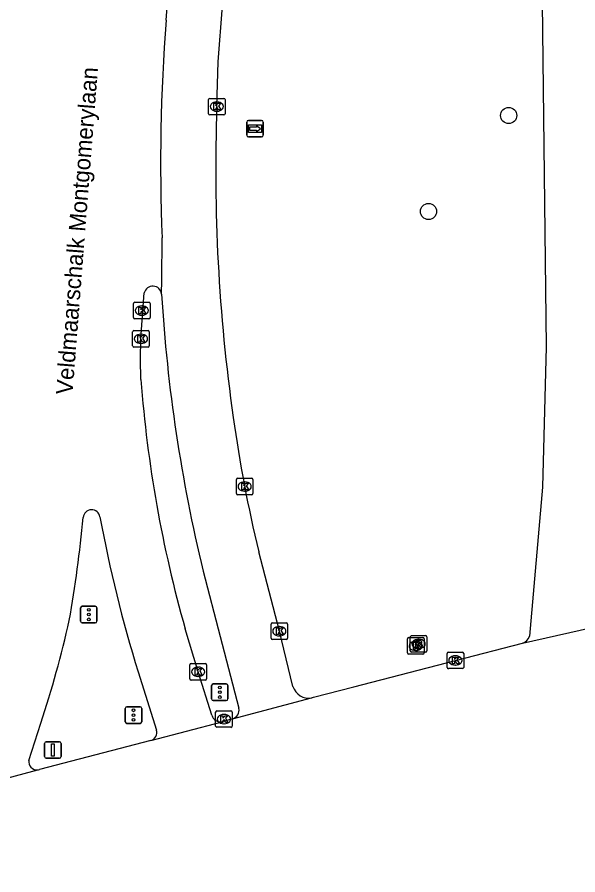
# Model space of a CAD drawing. Extents: x 160806 to 161707, y 383697 to 384148.
# Drawn here: x 161203.1 to 161236.9, y 383921.9 to 383973.8 of the extents above; entities that cross this region are included whole.
import ezdxf

# ---------------------------------------------------------------- set-up
doc = ezdxf.new("R2010")
doc.units = 0
for name, color, linetype in [('IMGEO_Boom', 7, 'Continuous'), ('IMGEO_Kolk', 7, 'Continuous'), ('IMGEO_Openbare_ruimte_label', 7, 'Continuous'), ('IMGEO_OVBaan_gesloten', 7, 'Continuous'), ('IMGEO_Portaal', 7, 'Continuous'), ('IMGEO_Rijbaan_lokaal_gesloten', 7, 'Continuous'), ('IMGEO_Rioolput', 7, 'Continuous'), ('IMGEO_Verkeersregelinstallatiepaal', 7, 'Continuous'), ('IMGEO_Wegwijzer', 7, 'Continuous')]:
    doc.layers.add(name, color=color, linetype=linetype)

msp = doc.modelspace()

# ---------------------------------------------------------------- linework, layer by layer
at = {"layer": 'IMGEO_Boom'}
for centre in [(161232.756, 383967.827), (161227.918, 383962.027)]:
    msp.add_circle(centre, 0.489, dxfattribs=at)
at = {"layer": 'IMGEO_Kolk'}
for p, q in [((161214.636, 383967.938), (161214.636, 383968.79)), ((161214.711, 383968.864), (161215.563, 383968.864)), ((161215.124, 383968.644), (161215.149, 383968.644)), ((161215.637, 383968.79), (161215.637, 383967.938)), ((161215.147, 383968.084), (161215.122, 383968.084)), ((161215.563, 383967.864), (161214.711, 383967.864)), ((161210.106, 383955.61), (161210.106, 383956.462)), ((161210.181, 383956.536), (161211.033, 383956.536)), ((161210.594, 383956.316), (161210.619, 383956.316)), ((161211.107, 383956.462), (161211.107, 383955.61)), ((161210.617, 383955.756), (161210.592, 383955.756)), ((161211.033, 383955.536), (161210.181, 383955.536)), ((161210.051, 383953.904), (161210.051, 383954.756)), ((161210.126, 383954.83), (161210.978, 383954.83)), ((161210.539, 383954.61), (161210.564, 383954.61)), ((161211.052, 383954.756), (161211.052, 383953.904)), ((161210.978, 383953.83), (161210.126, 383953.83)), ((161210.562, 383954.05), (161210.537, 383954.05)), ((161216.313, 383944.977), (161216.313, 383945.829)), ((161216.388, 383945.903), (161217.24, 383945.903)), ((161217.314, 383945.829), (161217.314, 383944.977)), ((161216.801, 383945.683), (161216.826, 383945.683)), ((161217.24, 383944.903), (161216.388, 383944.903)), ((161216.824, 383945.123), (161216.799, 383945.123)), ((161218.408, 383936.232), (161218.408, 383937.084)), ((161218.483, 383937.158), (161219.335, 383937.158)), ((161219.409, 383937.084), (161219.409, 383936.232)), ((161218.896, 383936.938), (161218.921, 383936.938)), ((161219.335, 383936.158), (161218.483, 383936.158)), ((161218.919, 383936.378), (161218.894, 383936.378)), ((161229.041, 383934.469), (161229.041, 383935.321)), ((161229.116, 383935.395), (161229.968, 383935.395)), ((161229.529, 383935.175), (161229.554, 383935.175)), ((161230.042, 383935.321), (161230.042, 383934.469)), ((161213.508, 383933.781), (161213.508, 383934.633)), ((161213.583, 383934.707), (161214.435, 383934.707)), ((161213.996, 383934.487), (161214.021, 383934.487)), ((161214.509, 383934.633), (161214.509, 383933.781)), ((161229.968, 383934.395), (161229.116, 383934.395)), ((161229.552, 383934.615), (161229.527, 383934.615)), ((161214.019, 383933.927), (161213.994, 383933.927)), ((161214.435, 383933.707), (161213.583, 383933.707)), ((161215.137, 383931.849), (161215.989, 383931.849)), ((161215.062, 383930.923), (161215.062, 383931.775)), ((161215.55, 383931.629), (161215.575, 383931.629)), ((161216.063, 383931.775), (161216.063, 383930.923)), ((161215.989, 383930.849), (161215.137, 383930.849)), ((161215.573, 383931.069), (161215.548, 383931.069))]:
    msp.add_line(p, q, dxfattribs=at)
for points in [[(161214.636, 383967.938), (161214.636, 383968.79)], [(161214.711, 383968.864), (161215.563, 383968.864)], [(161215.637, 383968.79), (161215.637, 383967.938)], [(161214.957, 383968.564), (161215.08, 383968.564), (161215.08, 383968.413), (161215.21, 383968.564), (161215.374, 383968.564), (161215.228, 383968.413), (161215.381, 383968.164), (161215.229, 383968.164), (161215.144, 383968.328), (161215.08, 383968.261), (161215.08, 383968.164), (161214.957, 383968.164), (161214.957, 383968.564)], [(161215.563, 383967.864), (161214.711, 383967.864)], [(161210.106, 383955.61), (161210.106, 383956.462)], [(161210.181, 383956.536), (161211.033, 383956.536)], [(161210.427, 383956.236), (161210.55, 383956.236), (161210.55, 383956.085), (161210.68, 383956.236), (161210.844, 383956.236), (161210.698, 383956.085), (161210.851, 383955.836), (161210.699, 383955.836), (161210.614, 383956), (161210.55, 383955.933), (161210.55, 383955.836), (161210.427, 383955.836), (161210.427, 383956.236)], [(161211.107, 383956.462), (161211.107, 383955.61)], [(161211.033, 383955.536), (161210.181, 383955.536)], [(161210.051, 383953.904), (161210.051, 383954.756)], [(161210.126, 383954.83), (161210.978, 383954.83)], [(161211.052, 383954.756), (161211.052, 383953.904)], [(161210.372, 383954.53), (161210.495, 383954.53), (161210.495, 383954.379), (161210.625, 383954.53), (161210.789, 383954.53), (161210.643, 383954.379), (161210.796, 383954.13), (161210.644, 383954.13), (161210.559, 383954.294), (161210.495, 383954.227), (161210.495, 383954.13), (161210.372, 383954.13), (161210.372, 383954.53)], [(161210.978, 383953.83), (161210.126, 383953.83)], [(161216.313, 383944.977), (161216.313, 383945.829)], [(161216.388, 383945.903), (161217.24, 383945.903)], [(161217.314, 383945.829), (161217.314, 383944.977)], [(161216.634, 383945.603), (161216.757, 383945.603), (161216.757, 383945.452), (161216.887, 383945.603), (161217.051, 383945.603), (161216.905, 383945.452), (161217.058, 383945.203), (161216.906, 383945.203), (161216.821, 383945.367), (161216.757, 383945.3), (161216.757, 383945.203), (161216.634, 383945.203), (161216.634, 383945.603)], [(161217.24, 383944.903), (161216.388, 383944.903)], [(161218.408, 383936.232), (161218.408, 383937.084)], [(161218.483, 383937.158), (161219.335, 383937.158)], [(161219.409, 383937.084), (161219.409, 383936.232)], [(161218.729, 383936.858), (161218.852, 383936.858), (161218.852, 383936.707), (161218.982, 383936.858), (161219.146, 383936.858), (161219, 383936.707), (161219.153, 383936.458), (161219.001, 383936.458), (161218.916, 383936.622), (161218.852, 383936.555), (161218.852, 383936.458), (161218.729, 383936.458), (161218.729, 383936.858)], [(161219.335, 383936.158), (161218.483, 383936.158)], [(161229.041, 383934.469), (161229.041, 383935.321)], [(161229.116, 383935.395), (161229.968, 383935.395)], [(161229.362, 383935.095), (161229.485, 383935.095), (161229.485, 383934.944), (161229.615, 383935.095), (161229.779, 383935.095), (161229.633, 383934.944), (161229.786, 383934.695), (161229.634, 383934.695), (161229.549, 383934.859), (161229.485, 383934.792), (161229.485, 383934.695), (161229.362, 383934.695), (161229.362, 383935.095)], [(161230.042, 383935.321), (161230.042, 383934.469)], [(161213.508, 383933.781), (161213.508, 383934.633)], [(161213.583, 383934.707), (161214.435, 383934.707)], [(161213.829, 383934.407), (161213.952, 383934.407), (161213.952, 383934.256), (161214.082, 383934.407), (161214.246, 383934.407), (161214.1, 383934.256), (161214.253, 383934.007), (161214.101, 383934.007), (161214.016, 383934.171), (161213.952, 383934.104), (161213.952, 383934.007), (161213.829, 383934.007), (161213.829, 383934.407)], [(161214.509, 383934.633), (161214.509, 383933.781)], [(161229.968, 383934.395), (161229.116, 383934.395)], [(161214.435, 383933.707), (161213.583, 383933.707)], [(161215.137, 383931.849), (161215.989, 383931.849)], [(161215.062, 383930.923), (161215.062, 383931.775)], [(161215.383, 383931.549), (161215.506, 383931.549), (161215.506, 383931.398), (161215.636, 383931.549), (161215.8, 383931.549), (161215.654, 383931.398), (161215.807, 383931.149), (161215.655, 383931.149), (161215.57, 383931.313), (161215.506, 383931.246), (161215.506, 383931.149), (161215.383, 383931.149), (161215.383, 383931.549)], [(161216.063, 383931.775), (161216.063, 383930.923)], [(161215.989, 383930.849), (161215.137, 383930.849)]]:
    msp.add_lwpolyline(points, dxfattribs=at)
for centre, start, end in [((161214.713, 383968.788), 91.552, 178.448), ((161214.713, 383968.788), 91.552, 178.448), ((161215.561, 383968.788), 1.552, 88.448), ((161215.561, 383968.788), 1.552, 88.448), ((161214.713, 383967.94), 181.552, 268.448), ((161214.713, 383967.94), 181.552, 268.448), ((161215.561, 383967.94), 271.552, 358.448), ((161215.561, 383967.94), 271.552, 358.448), ((161210.183, 383956.46), 91.552, 178.448), ((161210.183, 383956.46), 91.552, 178.448), ((161211.031, 383956.46), 1.552, 88.448), ((161211.031, 383956.46), 1.552, 88.448), ((161210.183, 383955.612), 181.552, 268.448), ((161210.183, 383955.612), 181.552, 268.448), ((161211.031, 383955.612), 271.552, 358.448), ((161211.031, 383955.612), 271.552, 358.448), ((161210.128, 383954.754), 91.552, 178.448), ((161210.128, 383954.754), 91.552, 178.448), ((161210.976, 383954.754), 1.552, 88.448), ((161210.976, 383954.754), 1.552, 88.448), ((161210.128, 383953.906), 181.552, 268.448), ((161210.128, 383953.906), 181.552, 268.448), ((161210.976, 383953.906), 271.552, 358.448), ((161210.976, 383953.906), 271.552, 358.448), ((161216.39, 383945.827), 91.552, 178.448), ((161216.39, 383945.827), 91.552, 178.448), ((161217.238, 383945.827), 1.552, 88.448), ((161217.238, 383945.827), 1.552, 88.448), ((161216.39, 383944.979), 181.552, 268.448), ((161216.39, 383944.979), 181.552, 268.448), ((161217.238, 383944.979), 271.552, 358.448), ((161217.238, 383944.979), 271.552, 358.448), ((161218.485, 383937.082), 91.552, 178.448), ((161218.485, 383937.082), 91.552, 178.448), ((161219.333, 383937.082), 1.552, 88.448), ((161219.333, 383937.082), 1.552, 88.448), ((161218.485, 383936.234), 181.552, 268.448), ((161218.485, 383936.234), 181.552, 268.448), ((161219.333, 383936.234), 271.552, 358.448), ((161219.333, 383936.234), 271.552, 358.448), ((161229.118, 383935.319), 91.552, 178.448), ((161229.118, 383935.319), 91.552, 178.448), ((161229.966, 383935.319), 1.552, 88.448), ((161229.966, 383935.319), 1.552, 88.448), ((161213.585, 383934.631), 91.552, 178.448), ((161213.585, 383934.631), 91.552, 178.448), ((161214.433, 383934.631), 1.552, 88.448), ((161214.433, 383934.631), 1.552, 88.448), ((161229.118, 383934.471), 181.552, 268.448), ((161229.118, 383934.471), 181.552, 268.448), ((161229.966, 383934.471), 271.552, 358.448), ((161229.966, 383934.471), 271.552, 358.448), ((161213.585, 383933.783), 181.552, 268.448), ((161213.585, 383933.783), 181.552, 268.448), ((161214.433, 383933.783), 271.552, 358.448), ((161214.433, 383933.783), 271.552, 358.448), ((161215.139, 383931.773), 91.552, 178.448), ((161215.139, 383931.773), 91.552, 178.448), ((161215.987, 383931.773), 1.552, 88.448), ((161215.987, 383931.773), 1.552, 88.448), ((161215.139, 383930.925), 181.552, 268.448), ((161215.139, 383930.925), 181.552, 268.448), ((161215.987, 383930.925), 271.552, 358.448), ((161215.987, 383930.925), 271.552, 358.448)]:
    msp.add_arc(centre, 0.0765, start, end, dxfattribs=at)
for centre, major_axis, ratio, start_param, end_param in [((161215.123, 383968.364), (-0.387, 0.002), 0.722429, 4.712389, 7.853982), ((161215.148, 383968.364), (-0.39, 0.002), 0.717154, 1.570796, 4.712389), ((161210.593, 383956.036), (-0.387, 0.002), 0.722429, 4.712389, 7.853982), ((161210.618, 383956.036), (-0.39, 0.002), 0.717154, 1.570796, 4.712389), ((161210.538, 383954.33), (-0.387, 0.002), 0.722429, 4.712389, 7.853982), ((161210.563, 383954.33), (-0.39, 0.002), 0.717154, 1.570796, 4.712389), ((161216.8, 383945.403), (-0.387, 0.002), 0.722429, 4.712389, 7.853982), ((161216.825, 383945.403), (-0.39, 0.002), 0.717154, 1.570796, 4.712389), ((161218.895, 383936.658), (-0.387, 0.002), 0.722429, 4.712389, 7.853982), ((161218.92, 383936.658), (-0.39, 0.002), 0.717154, 1.570796, 4.712389), ((161229.528, 383934.895), (-0.387, 0.002), 0.722429, 4.712389, 7.853982), ((161229.553, 383934.895), (-0.39, 0.002), 0.717154, 1.570796, 4.712389), ((161213.995, 383934.207), (-0.387, 0.002), 0.722429, 4.712389, 7.853982), ((161214.02, 383934.207), (-0.39, 0.002), 0.717154, 1.570796, 4.712389), ((161215.549, 383931.349), (-0.387, 0.002), 0.722429, 4.712389, 7.853982), ((161215.574, 383931.349), (-0.39, 0.002), 0.717154, 1.570796, 4.712389)]:
    msp.add_ellipse(centre, major_axis=major_axis, ratio=ratio, start_param=start_param, end_param=end_param, dxfattribs=at)
at = {"layer": 'IMGEO_OVBaan_gesloten'}
for points in [[(161212.071, 383973.586), (161214.441, 384004.323)], [(161215.137, 383968.364), (161215.222, 383971.062), (161216.53, 383988.019), (161217.59, 384002.154)], [(161211.793, 383957.036), (161211.811, 383957.889), (161211.83, 383960.427)], [(161219.729, 383933.32), (161218.909, 383936.658), (161217.663, 383941.452)], [(161214.31, 383940.287), (161215.337, 383936.331), (161216.466, 383931.999)], [(161216.084, 383931.37), (161220.861, 383932.636)]]:
    msp.add_lwpolyline(points, dxfattribs=at)
for centre, radius, start, end in [((161322.247, 383964.986), 110.511, 175.53696, 182.36459), ((161320.498, 383964.509), 105.432, 177.9047, 188.14488), ((161307.986, 383962.928), 96.373, 183.50511, 193.58753), ((161299.612, 383961.128), 84.278, 187.88118, 193.50125), ((161220.669, 383933.597), 0.98, 196.3992, 281.3167), ((161215.942, 383931.887), 0.536, 285.3781, 12.0801)]:
    msp.add_arc(centre, radius, start, end, dxfattribs=at)
at = {"layer": 'IMGEO_Portaal'}
for p, q in [((161204.737, 383929.08), (161204.737, 383929.88)), ((161204.737, 383929.88), (161204.737, 383929.08)), ((161204.837, 383929.98), (161205.627, 383929.98)), ((161205.627, 383929.98), (161204.837, 383929.98)), ((161205.727, 383929.88), (161205.727, 383929.08)), ((161205.727, 383929.08), (161205.727, 383929.88)), ((161205.627, 383928.98), (161204.837, 383928.98)), ((161204.837, 383928.98), (161205.627, 383928.98))]:
    msp.add_line(p, q, dxfattribs=at)
msp.add_lwpolyline([(161205.157, 383929.855), (161205.307, 383929.855), (161205.307, 383929.105), (161205.157, 383929.105), (161205.157, 383929.855)], dxfattribs=at)
for centre, start, end in [((161204.837, 383929.88), 90, 180), ((161204.837, 383929.88), 90, 180), ((161205.627, 383929.88), 0, 90), ((161205.627, 383929.88), 360, 90), ((161204.837, 383929.08), 180, 270), ((161204.837, 383929.08), 180, 270), ((161205.627, 383929.08), 270, 0), ((161205.627, 383929.08), 270, 0)]:
    msp.add_arc(centre, 0.1, start, end, dxfattribs=at)
at = {"layer": 'IMGEO_Rijbaan_lokaal_gesloten'}
for points in [[(161234.263, 384024.171), (161234.492, 383998.945), (161235.013, 383953.847), (161234.793, 383945.355), (161234.023, 383936.363)], [(161210.551, 383951.863), (161210.527, 383953.098), (161210.552, 383954.33), (161210.749, 383957.101)], [(161233.595, 383935.943), (161251.997, 383940.077)], [(161214.826, 383931.579), (161214.009, 383934.207), (161213.226, 383936.804)], [(161220.861, 383932.636), (161220.976, 383932.667), (161223.402, 383933.299), (161229.542, 383934.895), (161233.595, 383935.943)], [(161210.386, 383934.199), (161211.485, 383930.681)], [(161216.084, 383931.37), (161215.456, 383931.183)], [(161203.779, 383928.854), (161204.51, 383931.103)], [(161211.147, 383930.051), (161215.456, 383931.183)], [(161211.147, 383930.051), (161204.418, 383928.292)], [(161178.402, 383921.933), (161183.781, 383922.753), (161204.32, 383928.275)]]:
    msp.add_lwpolyline(points, dxfattribs=at)
for centre, radius, start, end in [((161211.266, 383956.986), 0.53, 5.4349, 167.4397), ((161286.07, 383957.511), 75.73, 184.27689, 195.86841), ((161207.572, 383943.487), 0.512, 9.1292, 174.7041), ((161132.556, 383950.401), 74.822, 349.92486, 354.73388), ((161286.065, 383957.811), 79.277, 190.34993, 197.32795), ((161140.112, 383952.221), 67.772, 341.84401, 347.29156), ((161233.438, 383936.531), 0.609, 284.9675, 343.9515), ((161215.357, 383931.724), 0.55, 195.3077, 280.3877), ((161211.017, 383930.527), 0.493, 285.3402, 18.232), ((161204.282, 383928.781), 0.508, 171.7914, 274.3222), ((161204.283, 383928.777), 0.503, 274.1696, 285.5126)]:
    msp.add_arc(centre, radius, start, end, dxfattribs=at)
at = {"layer": 'IMGEO_Rioolput'}
for p, q in [((161226.646, 383935.347), (161226.646, 383936.199)), ((161226.721, 383936.273), (161227.573, 383936.273)), ((161226.817, 383935.464), (161226.817, 383936.316)), ((161226.892, 383936.39), (161227.744, 383936.39)), ((161227.134, 383936.053), (161227.159, 383936.053)), ((161227.305, 383936.17), (161227.33, 383936.17)), ((161227.647, 383936.199), (161227.647, 383935.347)), ((161227.818, 383936.316), (161227.818, 383935.464)), ((161227.157, 383935.493), (161227.132, 383935.493)), ((161227.328, 383935.61), (161227.303, 383935.61)), ((161227.573, 383935.273), (161226.721, 383935.273)), ((161227.744, 383935.39), (161226.892, 383935.39))]:
    msp.add_line(p, q, dxfattribs=at)
for points in [[(161226.646, 383935.347), (161226.646, 383936.199)], [(161226.721, 383936.273), (161227.573, 383936.273)], [(161226.817, 383935.464), (161226.817, 383936.316)], [(161226.892, 383936.39), (161227.744, 383936.39)], [(161227.235, 383935.971), (161226.983, 383935.973), (161226.983, 383935.573)], [(161227.406, 383936.088), (161227.154, 383936.09), (161227.154, 383935.69)], [(161227.332, 383936.009), (161227.278, 383936.009), (161227.278, 383935.928)], [(161227.647, 383936.199), (161227.647, 383935.347)], [(161227.818, 383936.316), (161227.818, 383935.464)], [(161226.983, 383935.573), (161227.107, 383935.573), (161227.107, 383935.735), (161227.118, 383935.735)], [(161227.161, 383935.892), (161227.107, 383935.892), (161227.107, 383935.811)], [(161227.107, 383935.811), (161227.159, 383935.811)], [(161227.154, 383935.69), (161227.278, 383935.69), (161227.278, 383935.852), (161227.289, 383935.852)], [(161227.165, 383935.706), (161227.236, 383935.573), (161227.376, 383935.573), (161227.311, 383935.699)], [(161227.278, 383935.928), (161227.33, 383935.928)], [(161227.336, 383935.823), (161227.407, 383935.69), (161227.547, 383935.69), (161227.482, 383935.816)], [(161227.573, 383935.273), (161226.721, 383935.273)], [(161227.744, 383935.39), (161226.892, 383935.39)]]:
    msp.add_lwpolyline(points, dxfattribs=at)
for centre, radius, start, end in [((161226.723, 383936.197), 0.0765, 91.552, 178.448), ((161226.723, 383936.197), 0.0765, 91.552, 178.448), ((161226.894, 383936.314), 0.0765, 91.552, 178.448), ((161226.894, 383936.314), 0.0765, 91.552, 178.448), ((161227.234, 383935.861), 0.109, 350.3612, 89.416), ((161227.338, 383935.913), 0.0964, 77.0061, 93.1865), ((161227.352, 383935.97), 0.0378, 276.6634, 79.6772), ((161227.405, 383935.978), 0.109, 350.3612, 89.416), ((161227.403, 383935.978), 0.112, 277.5842, 350.9817), ((161227.571, 383936.197), 0.0765, 1.552, 88.448), ((161227.571, 383936.197), 0.0765, 1.552, 88.448), ((161227.742, 383936.314), 0.0765, 1.552, 88.448), ((161227.742, 383936.314), 0.0765, 1.552, 88.448), ((161226.894, 383935.466), 0.0765, 181.552, 268.448), ((161226.894, 383935.466), 0.0765, 181.552, 268.448), ((161227.117, 383935.682), 0.0533, 26.0293, 88.6989), ((161227.143, 383936), 0.19, 274.7715, 282.9687), ((161227.167, 383935.796), 0.0964, 77.0061, 93.1865), ((161227.181, 383935.853), 0.0378, 276.6634, 79.6772), ((161227.232, 383935.861), 0.112, 277.5842, 350.9817), ((161227.216, 383935.646), 0.108, 29.5134, 73.7905), ((161227.288, 383935.799), 0.0533, 26.0293, 88.6989), ((161227.314, 383936.117), 0.19, 274.7715, 282.9687), ((161227.387, 383935.763), 0.108, 29.5134, 73.7905), ((161227.742, 383935.466), 0.0765, 271.552, 358.448), ((161227.742, 383935.466), 0.0765, 271.552, 358.448), ((161226.723, 383935.349), 0.0765, 181.552, 268.448), ((161226.723, 383935.349), 0.0765, 181.552, 268.448), ((161227.571, 383935.349), 0.0765, 271.552, 358.448), ((161227.571, 383935.349), 0.0765, 271.552, 358.448)]:
    msp.add_arc(centre, radius, start, end, dxfattribs=at)
for centre, major_axis, ratio, start_param, end_param in [((161227.133, 383935.773), (-0.387, 0.002), 0.722429, 4.712389, 7.853982), ((161227.304, 383935.89), (-0.387, 0.002), 0.722429, 4.712389, 7.853982), ((161227.158, 383935.773), (-0.39, 0.002), 0.717154, 1.570796, 4.712389), ((161227.329, 383935.89), (-0.39, 0.002), 0.717154, 1.570796, 4.712389)]:
    msp.add_ellipse(centre, major_axis=major_axis, ratio=ratio, start_param=start_param, end_param=end_param, dxfattribs=at)
at = {"layer": 'IMGEO_Verkeersregelinstallatiepaal'}
for p, q in [((161206.906, 383937.264), (161206.906, 383938.064)), ((161206.906, 383938.064), (161206.906, 383937.264)), ((161207.006, 383938.164), (161207.796, 383938.164)), ((161207.796, 383938.164), (161207.006, 383938.164)), ((161207.896, 383938.064), (161207.896, 383937.264)), ((161207.896, 383937.264), (161207.896, 383938.064)), ((161207.796, 383937.164), (161207.006, 383937.164)), ((161207.006, 383937.164), (161207.796, 383937.164)), ((161214.816, 383932.571), (161214.816, 383933.371)), ((161214.816, 383933.371), (161214.816, 383932.571)), ((161214.916, 383933.471), (161215.706, 383933.471)), ((161215.706, 383933.471), (161214.916, 383933.471)), ((161215.806, 383933.371), (161215.806, 383932.571)), ((161215.806, 383932.571), (161215.806, 383933.371)), ((161215.706, 383932.471), (161214.916, 383932.471)), ((161214.916, 383932.471), (161215.706, 383932.471)), ((161209.606, 383931.187), (161209.606, 383931.987)), ((161209.606, 383931.987), (161209.606, 383931.187)), ((161209.706, 383932.087), (161210.496, 383932.087)), ((161210.496, 383932.087), (161209.706, 383932.087)), ((161210.596, 383931.987), (161210.596, 383931.187)), ((161210.596, 383931.187), (161210.596, 383931.987)), ((161210.496, 383931.087), (161209.706, 383931.087)), ((161209.706, 383931.087), (161210.496, 383931.087))]:
    msp.add_line(p, q, dxfattribs=at)
for centre in [(161207.401, 383937.954), (161207.401, 383937.664), (161207.401, 383937.374), (161215.311, 383933.261), (161215.311, 383932.971), (161215.311, 383932.681), (161210.101, 383931.877), (161210.101, 383931.587), (161210.101, 383931.297)]:
    msp.add_circle(centre, 0.085, dxfattribs=at)
for centre, start, end in [((161207.006, 383938.064), 90, 180), ((161207.006, 383938.064), 90, 180), ((161207.796, 383938.064), 0, 90), ((161207.796, 383938.064), 360, 90), ((161207.006, 383937.264), 180, 270), ((161207.006, 383937.264), 180, 270), ((161207.796, 383937.264), 270, 0), ((161207.796, 383937.264), 270, 0), ((161214.916, 383933.371), 90, 180), ((161214.916, 383933.371), 90, 180), ((161215.706, 383933.371), 0, 90), ((161215.706, 383933.371), 360, 90), ((161214.916, 383932.571), 180, 270), ((161214.916, 383932.571), 180, 270), ((161215.706, 383932.571), 270, 0), ((161215.706, 383932.571), 270, 0), ((161209.706, 383931.987), 90, 180), ((161209.706, 383931.987), 90, 180), ((161210.496, 383931.987), 0, 90), ((161210.496, 383931.987), 360, 90), ((161209.706, 383931.187), 180, 270), ((161209.706, 383931.187), 180, 270), ((161210.496, 383931.187), 270, 0), ((161210.496, 383931.187), 270, 0)]:
    msp.add_arc(centre, 0.1, start, end, dxfattribs=at)
at = {"layer": 'IMGEO_Wegwijzer'}
for p, q in [((161216.943, 383966.631), (161216.943, 383967.431)), ((161216.943, 383967.431), (161216.943, 383966.631)), ((161217.043, 383967.531), (161217.833, 383967.531)), ((161217.833, 383967.531), (161217.043, 383967.531)), ((161217.933, 383967.431), (161217.933, 383966.631)), ((161217.933, 383966.631), (161217.933, 383967.431)), ((161217.833, 383966.531), (161217.043, 383966.531)), ((161217.043, 383966.531), (161217.833, 383966.531))]:
    msp.add_line(p, q, dxfattribs=at)
for points in [[(161217.044, 383967.263), (161217.832, 383967.263), (161217.832, 383966.799), (161217.044, 383966.799), (161217.044, 383967.263)], [(161217.109, 383967.115), (161217.109, 383967.031), (161217.109, 383966.947), (161217.52, 383966.947), (161217.52, 383966.864), (161217.767, 383967.031), (161217.52, 383967.198), (161217.52, 383967.115), (161217.109, 383967.115)]]:
    msp.add_lwpolyline(points, dxfattribs=at)
for centre, start, end in [((161217.043, 383967.431), 90, 180), ((161217.043, 383967.431), 90, 180), ((161217.833, 383967.431), 0, 90), ((161217.833, 383967.431), 360, 90), ((161217.043, 383966.631), 180, 270), ((161217.043, 383966.631), 180, 270), ((161217.833, 383966.631), 270, 0), ((161217.833, 383966.631), 270, 0)]:
    msp.add_arc(centre, 0.1, start, end, dxfattribs=at)

# ---------------------------------------------------------------- texts
at = {"layer": 'IMGEO_Openbare_ruimte_label'}
msp.add_text('Veldmaarschalk Montgomerylaan', height=1, rotation=85.5266, dxfattribs=at).set_placement((161206.413, 383950.928))

doc.saveas('drawing.dxf')
